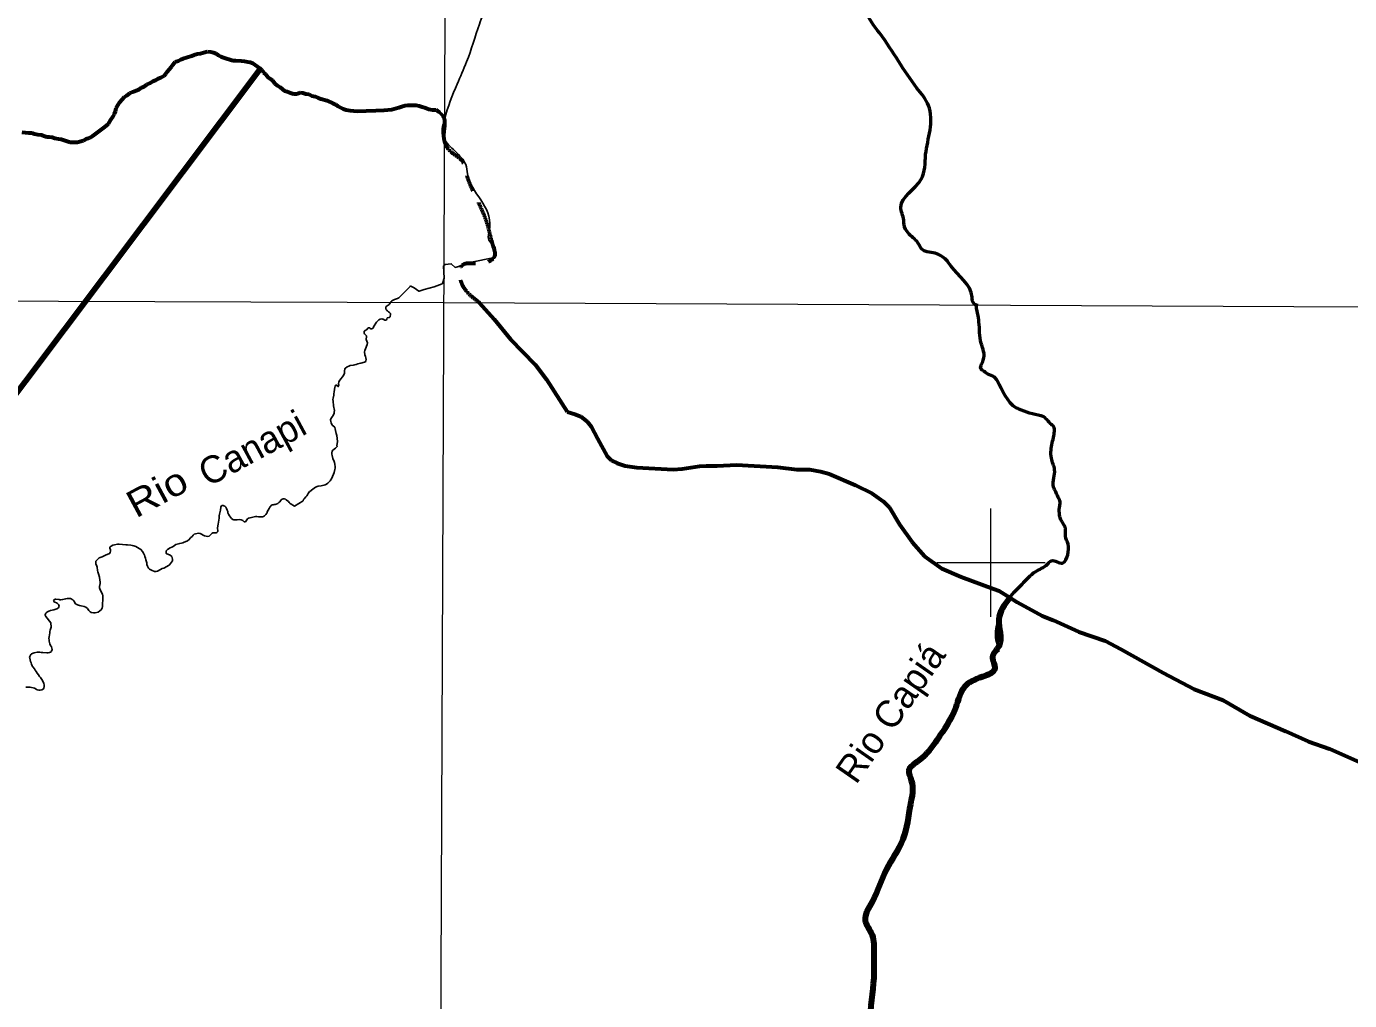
# Model space of a CAD drawing. Extents: x 553962 to 842807, y 8883888 to 9032388.
# Drawn here: x 657184 to 681625, y 8991910 to 9009903 of the extents above; entities that cross this region are included whole.
import ezdxf
from ezdxf.enums import TextEntityAlignment as Align

# ---------------------------------------------------------------- set-up
doc = ezdxf.new("R2010")
doc.units = 0
doc.header["$LTSCALE"] = 200
doc.linetypes.add('LONG_DASH_SHORT_DASH', pattern=[9.9, 6, -1.2, 1.5, -1.2])
for name, color, linetype, lineweight in [('1', 7, 'Continuous', 13), ('2', 7, 'Continuous', 13), ('24', 7, 'Continuous', 25), ('7', 7, 'LONG_DASH_SHORT_DASH', 60), ('9', 7, 'Continuous', 90)]:
    doc.layers.add(name, color=color, linetype=linetype, lineweight=lineweight)
doc.layers.add('49', color=7, linetype='Continuous')

msp = doc.modelspace()

# ---------------------------------------------------------------- linework, layer by layer
at = {"layer": '1'}
for points in [[(664968.2, 9023436.8), (664657.1, 8949509), (664397.1, 8890880.2)], [(565303.2, 9005146.6), (664889.8, 9004806.7), (719872.1, 9004543.9), (790635.8, 9004109)]]:
    msp.add_lwpolyline(points, dxfattribs=at)
at = {"layer": '2'}
for p, q in [((675000, 8999000), (675000, 9001000)), ((674000, 9000000), (676000, 9000000))]:
    msp.add_line(p, q, dxfattribs=at)
at = {"layer": '24'}
for points in [[(664888.7, 9005478.8), (664900.1, 9005251.2), (664869.8, 9005153.3), (664865.4, 9005145.8), (664717.4, 9005095.4), (664528.5, 9005045), (664441.2, 9005012.7), (664432.8, 9005015.5), (664343.5, 9005072.6), (664286.2, 9005107.2), (664280.8, 9005109), (664271.5, 9005101.5), (664208.7, 9005038.3), (664080.1, 9004905.7)], [(665798.1, 9005626.6), (665405.1, 9005550.8), (665165.6, 9005466.5), (665101.5, 9005450.6), (665032.2, 9005519.9), (664921.3, 9005506.1), (664888.7, 9005478.8)], [(664080.1, 9004905.7), (664063.5, 9004888.7), (664040.8, 9004876.6), (664021.9, 9004870), (663980.2, 9004861.2), (663946.3, 9004843.8), (663931.6, 9004832.2), (663929.7, 9004827.5), (663925.3, 9004825.6), (663922.8, 9004820.1), (663917.9, 9004815.5), (663910.5, 9004801.1), (663899, 9004783.8), (663883.9, 9004765), (663863.8, 9004751.9), (663845.5, 9004742.3), (663830.7, 9004729.4), (663824.8, 9004721.3), (663819.7, 9004702.6), (663823.3, 9004691.5), (663824.1, 9004683.3), (663832.8, 9004668.7), (663842.4, 9004656.8), (663854.1, 9004648.1), (663869.6, 9004633.8), (663887.6, 9004620.7), (663907, 9004598.9), (663907, 9004598.9), (663910.9, 9004584.5), (663902.4, 9004543.4), (663900.7, 9004539.3), (663881.2, 9004529), (663848.8, 9004520.2), (663839.5, 9004493.6), (663833.8, 9004483.1), (663820.7, 9004477), (663803.2, 9004478.8), (663774.4, 9004497.4), (663769.2, 9004499), (663746.7, 9004499.8), (663720.6, 9004496.7), (663695.8, 9004484.7), (663668.4, 9004461.3), (663648.1, 9004440.9), (663597.4, 9004352.2)], [(663597.4, 9004352.2), (663591.9, 9004338.7), (663585.2, 9004327.5), (663562, 9004318.3), (663545.8, 9004318.1), (663534.7, 9004324.6), (663525, 9004333.9), (663497.8, 9004335.9), (663473.3, 9004304.2), (663451.5, 9004291.8), (663425.3, 9004274.1), (663419.2, 9004251.7), (663419.6, 9004240.3), (663428.8, 9004227), (663461.2, 9004195.3), (663463.7, 9004190.3), (663466.9, 9004175.9), (663457.9, 9004121.1), (663483.9, 9004058.1), (663479.5, 9004030.4), (663444.7, 9003947.7), (663436.1, 9003919.8), (663430, 9003892.9), (663436.2, 9003836.4), (663444.6, 9003808.5), (663450.1, 9003780.8), (663459.3, 9003752.9), (663454.4, 9003726), (663450.1, 9003716.1), (663431.3, 9003702.2), (663360.9, 9003681.5), (663332.3, 9003676.8), (663305.3, 9003670.6), (663276.6, 9003659.9), (663248.8, 9003653.3), (663221, 9003644.9), (663165.3, 9003637.2), (663137.5, 9003629.7), (663109.8, 9003617.9), (663077.1, 9003593.6), (663073.8, 9003588.8), (663066.6, 9003572.2), (663061.7, 9003539.8), (663061.5, 9003511.9), (663059.4, 9003496.8), (663040.9, 9003457.1), (662971.2, 9003371.5), (662951.9, 9003338.4), (662948.3, 9003299.8), (662954, 9003282), (662947.1, 9003264.8), (662944, 9003251.6), (662942.9, 9003251.1), (662911.9, 9003278.6), (662899.6, 9003277.8), (662888.3, 9003260.5), (662879.6, 9003232.8), (662873.2, 9003204.9), (662866.8, 9003150.2), (662861.5, 9003121.4), (662858.9, 9003091.8), (662849.7, 9003038), (662846.5, 9003010.2), (662846.6, 9002979.2), (662855.1, 9002895.8), (662859.3, 9002866.8), (662868.7, 9002836.8), (662871.9, 9002808.7), (662871, 9002777.8), (662869.2, 9002761.2), (662849.1, 9002718.3), (662831.4, 9002691.2), (662805.1, 9002656.3), (662801.6, 9002634.7), (662804.8, 9002607.8), (662812, 9002578.7), (662832, 9002539.4), (662877.8, 9002502.9), (662881.5, 9002497.6), (662889.1, 9002470.7), (662893.7, 9002439.9), (662905.9, 9002382.7), (662915.2, 9002349), (662932.3, 9002238.2)], [(662932.3, 9002238.2), (662930.4, 9002232.8), (662918.7, 9002162.2), (662919.1, 9002158.4), (662924.3, 9002149.5), (662924.7, 9002146.9), (662910.5, 9002130.5), (662890.5, 9002112.2), (662844.9, 9002076.1), (662830.6, 9002055.4), (662824.1, 9002025.5), (662826.1, 9001999.9), (662830.2, 9001975), (662842.8, 9001924.6), (662865.6, 9001868.5), (662873.1, 9001845.7), (662878.6, 9001819.2), (662886, 9001766.9), (662885.8, 9001743), (662880.8, 9001718.2), (662866.3, 9001665.2), (662823, 9001561.5), (662795.5, 9001511.2), (662776.8, 9001488.3), (662751.1, 9001464.8), (662727, 9001447.9), (662703, 9001435.9), (662679.1, 9001427.9), (662625.9, 9001415.6), (662573.7, 9001409.9), (662524, 9001394.2), (662471, 9001354.5)], [(662471, 9001354.5), (662418, 9001314.7), (662413.9, 9001313.1), (662387.4, 9001275.2), (662375.4, 9001250.8), (662363.1, 9001233.2), (662344.9, 9001211.6), (662312, 9001177.4), (662303.6, 9001164.2), (662297.6, 9001142.3), (662132.9, 9001044.6), (662055.9, 9001090.7), (662051.5, 9001092.1), (662048.6, 9001095.2), (662046.8, 9001099.7), (662037.3, 9001108.4), (662022.2, 9001125.4), (661983.8, 9001159.7), (661966.6, 9001172.4), (661944.8, 9001178.8), (661926.5, 9001177.5), (661909.8, 9001173.8), (661901.4, 9001170.2), (661890.7, 9001159.3), (661864.8, 9001124.2), (661848.9, 9001108.4), (661829.4, 9001092.8), (661799.7, 9001079.5), (661781.2, 9001073.3), (661761.2, 9001070.8), (661742.7, 9001066.8), (661725.3, 9001066.6), (661721.3, 9001065.5), (661706.2, 9001054.2), (661685.2, 9001030.2), (661683.4, 9001024.9), (661678.4, 9001021.4), (661666.2, 9000995.9)], [(661666.2, 9000995.9), (661666, 9000995.8), (661628.2, 9000939.1), (661629.1, 9000923.3), (661621.8, 9000911.6), (661602.7, 9000889), (661580.6, 9000865.8), (661565.2, 9000853.8), (661545, 9000847.3), (661519.3, 9000842.1), (661468.8, 9000846.1), (661442.2, 9000850.3), (661414.8, 9000850.2), (661390.9, 9000847.2), (661313.8, 9000829), (661288.2, 9000820.3), (661264.1, 9000805.4), (661227.5, 9000755.1), (661208, 9000751.3), (661198.2, 9000757.5), (661179.9, 9000776.4), (661150.3, 9000789.5), (661123.7, 9000793.6), (661075.9, 9000790.6), (661048.4, 9000786.4), (661015, 9000789.2), (660997, 9000798), (660969.6, 9000815.2), (660936.1, 9000861.2), (660916.9, 9000893.2), (660906.5, 9000918), (660902.7, 9000944.6), (660893.5, 9000969.5), (660880.3, 9000995.9), (660864.7, 9001020.9), (660846.7, 9001041.3), (660832.8, 9001051.1), (660807.4, 9001057.7), (660797.2, 9001057), (660783.2, 9001044), (660772.5, 9001021.6), (660765.5, 9000968.5), (660747.9, 9000894.1), (660744.4, 9000865.7), (660743.2, 9000816.2), (660736.9, 9000789.6), (660730.5, 9000739.1), (660724.1, 9000712.6), (660715.8, 9000638.2), (660717.6, 9000586.8), (660716.8, 9000576.4), (660703.4, 9000556.3), (660691.2, 9000550.9), (660651.6, 9000550.6), (660627.7, 9000547.6), (660617, 9000544), (660613.3, 9000541.4), (660580.1, 9000504.8), (660556, 9000490), (660529.6, 9000484.5), (660503.9, 9000484.7), (660470.1, 9000491.9), (660394.1, 9000535.8), (660385, 9000538.7), (660360.5, 9000540.9), (660309.2, 9000533.2), (660284.4, 9000522.9), (660273.5, 9000516.3)], [(660273.5, 9000516.3), (660260.7, 9000503.6), (660242.4, 9000482.3), (660221.6, 9000464.5), (660179.6, 9000416.4), (660146.5, 9000396.3), (660098.7, 9000374.4), (660070.2, 9000365.5), (660046.2, 9000355.7), (660017.1, 9000352.3), (659968.3, 9000340.1), (659941.1, 9000330.8), (659916.1, 9000316.3), (659891.5, 9000299.3), (659868.5, 9000285.3), (659840.5, 9000274.1), (659791.5, 9000243.5), (659791.5, 9000243.5), (659764.1, 9000216.7)], [(659764.1, 9000216.7), (659766.6, 9000170.3), (659768.2, 9000165.1), (659774.5, 9000160.6), (659826.5, 9000142.5), (659840.8, 9000136.1), (659866.7, 9000114.8), (659877.4, 9000088.4), (659881.6, 9000062.4), (659881.8, 9000044.3), (659878.7, 9000033.4), (659825.5, 8999960), (659819.5, 8999953.8), (659723.2, 8999895.5), (659688.5, 8999887.8), (659659.7, 8999873.4), (659605.7, 8999841.4), (659576.1, 8999832.9), (659549.3, 8999836.2), (659494.5, 8999857.3), (659459.2, 8999876.8), (659440.5, 8999897.3), (659416.9, 8999934), (659408.9, 8999962.1), (659405.4, 8999993), (659391.8, 9000051.2), (659380, 9000082), (659373.4, 9000111.9), (659363.4, 9000140), (659357.1, 9000148.2), (659344.6, 9000173.6), (659327.4, 9000201.8), (659297.2, 9000242.3), (659268.6, 9000258.6), (659204.1, 9000299.8), (659165.9, 9000310.6), (659139.1, 9000316.3), (659110, 9000320.5), (659049.2, 9000326.1), (659018.4, 9000330.3), (658960.2, 9000334.5), (658898.5, 9000340.9), (658868.6, 9000338.6), (658809.5, 9000327), (658781.4, 9000320), (658750.4, 9000304), (658731.6, 9000292.7), (658725, 9000283.2), (658721, 9000274), (658723.2, 9000264.3), (658735.2, 9000237.8), (658736.5, 9000212.6), (658728.3, 9000183.5), (658719.9, 9000170.5), (658646.8, 9000134.5), (658582.1, 9000107.9), (658527.1, 9000087.1), (658500.7, 9000063.1), (658466.8, 9000023.7), (658464.3, 9000011.6), (658467.1, 8999971.4), (658475.8, 8999953.7), (658488.4, 8999914.2), (658494.9, 8999855.1), (658500.1, 8999826), (658513.6, 8999793.3), (658531.7, 8999732.1), (658538.8, 8999675.3), (658544, 8999643.4), (658543.9, 8999614.5), (658535.6, 8999557.6), (658535.5, 8999531.6), (658542.9, 8999498.1), (658590.6, 8999417.1), (658596.3, 8999388.5), (658593.3, 8999333.7), (658594.3, 8999302.9), (658591.1, 8999245.1), (658587, 8999215.1), (658587.8, 8999186), (658581.9, 8999159.2), (658571.8, 8999140.2), (658561.5, 8999126.8), (658537.9, 8999105.5), (658506.5, 8999084.8), (658451.1, 8999073.9), (658421.2, 8999073.9), (658391.5, 8999076.1), (658380.9, 8999077.9), (658363.2, 8999087.9), (658334.8, 8999114.2), (658310.6, 8999148.7), (658278.5, 8999178.4), (658249.9, 8999187.4), (658191.8, 8999200), (658161.8, 8999208.5), (658129.2, 8999220.1), (658104, 8999230.8), (658091.6, 8999239.2), (658060.2, 8999290.2), (658040.3, 8999310.8)], [(658040.3, 8999310.8), (658040.3, 8999310.8), (658000, 8999337.8), (657966.4, 8999338.9), (657938.3, 8999334), (657908.4, 8999330.6), (657878.4, 8999322.2), (657850.3, 8999317.1), (657817.7, 8999313.6), (657800.3, 8999313.7), (657787.5, 8999316.9), (657729.5, 8999326.2), (657712.2, 8999324.4), (657688.6, 8999307.5), (657685.1, 8999292.1), (657687.3, 8999285.1), (657693, 8999275.8), (657753.2, 8999252.7), (657775, 8999226.5), (657782.3, 8999211.3), (657785.2, 8999193), (657784.6, 8999178.2), (657773.8, 8999165.3), (657744.9, 8999144), (657690.9, 8999127.6), (657660.1, 8999123), (657630.1, 8999116.6), (657595.5, 8999103.3), (657562.7, 8999084.1), (657548.4, 8999069.4), (657544.1, 8999063.3), (657530.6, 8999033.5), (657531.1, 8999026), (657541, 8999005.5), (657634.2, 8998884.3), (657639.8, 8998808), (657621.8, 8998753.6), (657615.4, 8998727.9), (657612.9, 8998701.4), (657601.6, 8998627.3), (657600.2, 8998596.8), (657601.2, 8998573), (657604.3, 8998548.1), (657616.1, 8998496.8), (657628.2, 8998469.8), (657644.2, 8998443.7), (657653.9, 8998417.1), (657657.6, 8998393.2), (657648.4, 8998365.3), (657644.6, 8998359), (657626.4, 8998346.5), (657609.5, 8998339.4), (657584.9, 8998335.4), (657557.6, 8998334.5), (657484.2, 8998341.6), (657456.7, 8998341.8), (657430.2, 8998343.8), (657405.3, 8998342.9), (657378.8, 8998343.7), (657329.2, 8998335.4), (657279.9, 8998312.1), (657261.7, 8998299.4), (657250.3, 8998279.6), (657242.8, 8998249.8), (657243.3, 8998231.8), (657260.7, 8998173.6), (657272.5, 8998147), (657279.3, 8998120.5), (657289.5, 8998090.3), (657298.5, 8998083.2), (657303.2, 8998074.5), (657330.3, 8998035.7), (657345, 8998010.8), (657364.6, 8997987.5), (657384, 8997954.4), (657403.7, 8997929), (657426.3, 8997895.3), (657445.7, 8997875.4), (657467.3, 8997843.1), (657480.4, 8997819), (657504, 8997765.2), (657512, 8997741.1), (657513.1, 8997712.8), (657507.4, 8997682.2), (657504.9, 8997678.3), (657489.8, 8997663.3), (657464.9, 8997646.8), (657439.6, 8997643), (657411, 8997643.7), (657379.6, 8997651.8), (657363.8, 8997663.7), (657331.7, 8997680.8), (657249.9, 8997700.5), (657175.3, 8997701)]]:
    msp.add_lwpolyline(points, dxfattribs=at)
at = {"layer": '24', "lineweight": 53}
for points in [[(674726.7, 9004751), (674666.6, 9004817.9), (674653.2, 9004904.8), (674258.7, 9005480.2), (674171.8, 9005593.9), (674084.9, 9005660.8), (673971.2, 9005714.3), (673824.1, 9005741.1), (673750.6, 9005767.8), (673650.3, 9005908.3), (673469.7, 9006089), (673396.2, 9006242.8), (673389.5, 9006323.1), (673336, 9006563.9), (673714.2, 9007080), (673794.5, 9007534.9), (673874.7, 9007989.8), (673848, 9008444.8), (673634, 9008765.9), (672938.7, 9009782.8), (672724.7, 9010157.4), (673339.8, 9010746.1), (673527, 9010906.7), (673874.7, 9011040.5), (674008.4, 9011227.8), (673874.7, 9011896.8), (673981.7, 9012137.6), (674115.4, 9012271.4), (674222.4, 9012699.6), (673848, 9012699.6), (673500.3, 9012967.2), (672751.4, 9012886.9), (672564.2, 9013208), (672377, 9013341.8), (672243.3, 9013796.7), (672109.6, 9013957.3), (671868.9, 9014171.4), (671869.6, 9014455.6), (671949.9, 9014696.4), (672110.3, 9015231.6), (672244.1, 9015633), (672190.6, 9015820.4), (671869.6, 9015847.1), (671762.7, 9016088), (671495.2, 9016248.5), (671441.7, 9016596.4), (671094.1, 9016623.2), (670505.7, 9016837.2), (670211.5, 9016971), (670024.3, 9017265.4)], [(675154.1, 8998412.8), (675100.6, 8998680.4), (675187.5, 8999035), (675307.8, 8999295.9), (675575.3, 8999603.6), (675822.7, 8999831.1), (676043.3, 8999971.6), (676116.8, 9000031.8), (676324.1, 8999991.6), (676417.7, 9000145.5), (676424.4, 9000339.5), (676377.6, 9000486.7), (676377.6, 9000627.2), (676357.6, 9000680.7), (676277.3, 9000827.9), (676264, 9000914.9), (676270.6, 9001048.7), (676277.3, 9001122.2), (676243.9, 9001202.5), (676183.7, 9001339.3), (676157, 9001392.8), (676163.7, 9001566.7), (676177, 9001713.9), (676116.8, 9001928), (676110.2, 9002075.2), (676130.2, 9002209), (676163.7, 9002342.8), (676170.3, 9002389.6), (676150.3, 9002523.4), (676116.8, 9002550.2), (675949.7, 9002704), (675923, 9002710.7), (675515.1, 9002833.7), (675475, 9002853.7), (675113.9, 9003362.2), (675067.1, 9003422.4), (674940.1, 9003482.6), (674859.8, 9003542.8), (674819.7, 9003569.6), (674859.8, 9003736.8), (674819.7, 9004051.2), (674779.6, 9004439.2), (674752.9, 9004606.5), (674739.5, 9004773.7), (674742.2, 9004781.9)], [(673192.8, 8986819.2), (673266.9, 8987063), (672967.2, 8987378.4), (672888.4, 8987819.9), (673046.1, 8988482.3), (673345.7, 8989160.4), (673503.4, 8989586.2), (673377.3, 8989901.6), (673046.1, 8990153.9), (673014.5, 8990469.3), (673109.2, 8990705.9), (673156.5, 8990942.4), (672983, 8991115.9), (672793.8, 8991510.2), (672841.1, 8992330.2), (672841.1, 8992787.6), (672809.5, 8993118.7), (672683.4, 8993386.8), (672809.5, 8993733.8), (673077.6, 8994335.6), (673377.3, 8994887.9), (673519.2, 8995534.8), (673535, 8995976.6), (673487.7, 8996159.6), (673676.9, 8996349), (674008.1, 8996727.7), (674355, 8997327.2), (674512.7, 8997705.9), (674843.9, 8997895.2), (675080.4, 8998053), (675033.1, 8998242.4), (675144.3, 8998385.5)]]:
    msp.add_spline(points, degree=3, dxfattribs=at)
at = {"layer": '24'}
msp.add_spline([(665804.3, 9005643.1), (665835.9, 9005832.9), (665741, 9005927.8), (665741, 9006196.7), (665330, 9007177.5), (665298.4, 9007351.5), (665219.3, 9007478.1), (664982.2, 9007715.4), (664887.3, 9007841.9), (664903.2, 9008190), (665140.3, 9008838.5), (665314.2, 9009249.8), (665551.3, 9009945.9), (665693.6, 9010293.9), (665962.4, 9010752.7), (666088.8, 9010942.5), (666468.3, 9011179.8), (666547.3, 9011306.3), (666847.7, 9011844.2), (667100.6, 9012508.6), (667369.4, 9012714.2), (667733, 9012603.5)], degree=3, dxfattribs=at)
at = {"layer": '7'}
for points in [[(659209.3, 9008717), (659256.9, 9008739.8), (659309.5, 9008775.2), (659357.1, 9008795.4), (659404.7, 9008830.8), (659464.8, 9008856.2), (659519.9, 9008891.6), (659567.5, 9008909.3), (659615.1, 9008942.2), (659667.8, 9008962.5), (659725.4, 9008992.9), (659757.9, 9009030.7), (659787.8, 9009070.9), (659822.9, 9009106.2), (659865.3, 9009159.1), (659892.8, 9009199.4), (659930.3, 9009247.3), (659990.4, 9009270.1), (660038.1, 9009290.4), (660080.7, 9009313.2), (660236.1, 9009361.6), (660281.2, 9009379.3), (660341.4, 9009397.2), (660401.7, 9009402.5), (660459.3, 9009422.8), (660527.1, 9009438.2), (660589.8, 9009435.9), (660637.6, 9009421.1), (660685.4, 9009403.7), (660723.1, 9009373.8), (660773.5, 9009346.4), (660826.2, 9009326.5), (660997.2, 9009272.1), (661049.9, 9009272.3), (661152.8, 9009267.7), (661210.6, 9009263), (661270.9, 9009248.2), (661318.6, 9009243.4), (661363.9, 9009226), (661409.2, 9009193.6), (661452, 9009166.2), (661492.3, 9009133.7), (661532.6, 9009096.2), (661560.4, 9009051.2), (661608.2, 9009013.8), (661641.1, 9008966.2), (661691.4, 9008936.3), (661729.2, 9008903.9), (661774.6, 9008851.3), (661814.9, 9008811.4), (661867.8, 9008781.5), (661950.8, 9008716.6), (661998.6, 9008701.8), (662059, 9008674.4), (662116.8, 9008659.6), (662177, 9008659.9), (662242.2, 9008680.2), (662289.9, 9008675.4), (662347.7, 9008658.1), (662403, 9008653.3), (662458.3, 9008623.5), (662518.6, 9008606.2), (662574, 9008583.8), (662624.2, 9008566.5), (662734.8, 9008536.9), (662850.5, 9008479.7), (662898.3, 9008462.3), (662936.1, 9008432.3), (663034.2, 9008380.1), (663089.5, 9008362.8), (663162.3, 9008348), (663225.1, 9008343.3), (663290.4, 9008341.1), (663458.6, 9008341.8), (663636.8, 9008352.6), (663792.4, 9008358.3), (663932.9, 9008369), (664063.3, 9008404.7), (664121, 9008425.1), (664178.6, 9008442.9), (664231.3, 9008448.1), (664334.2, 9008448.6), (664384.5, 9008446.3), (664439.7, 9008439), (664492.5, 9008419.2), (664552.8, 9008401.9), (664615.7, 9008374.6), (664683.5, 9008364.8), (664748.7, 9008365.1)], [(657098.1, 9007949.5), (657221.2, 9007940.1), (657283.9, 9007937.8), (657331.7, 9007920.5), (657392, 9007908.2), (657459.9, 9007898.4), (657505.1, 9007881.1), (657557.9, 9007866.2), (657605.6, 9007861.4), (657655.9, 9007859.2), (657708.7, 9007841.8), (657776.5, 9007827.1), (657824.2, 9007822.2), (657990.2, 9007767.8), (658125.8, 9007768.4), (658236.1, 9007799), (658286.2, 9007829.3), (658346.4, 9007847.2), (658409, 9007885.1), (658461.6, 9007920.5), (658634.4, 9008049.3), (658702, 9008104.8), (658744.3, 9008180.3), (658786.8, 9008240.7), (658809.2, 9008288.5), (658826.6, 9008333.8), (658841.4, 9008396.6), (658876.3, 9008457), (658911.3, 9008504.8), (658993.8, 9008600.6), (659038.9, 9008628.4), (659096.5, 9008668.8), (659149.1, 9008696.6), (659209.3, 9008717)], [(665554.2, 9004795.8), (665826.3, 9004496), (666128.4, 9004129.5), (666582.2, 9003656.2), (666791.2, 9003384.4), (667173.5, 9002782.6), (667316.8, 9002742.9), (667422.9, 9002700.1), (667541.5, 9002608.8), (667614.9, 9002511.4), (667732.4, 9002291), (667913.5, 9001963.7), (667993.5, 9001885.6), (668093.1, 9001836.3), (668244.3, 9001789.9), (668460.2, 9001759), (669127.8, 9001717.8), (669295.7, 9001729.2), (669615.5, 9001778.1), (669741.5, 9001789.9), (669941.5, 9001784.9), (670299.8, 9001804.4), (671060.9, 9001759.2), (671415.5, 9001717.4), (671657.5, 9001718.6), (671854, 9001684.6), (672015, 9001638.1), (672500.4, 9001430.7), (672799.2, 9001283), (673014.1, 9001129.5), (673119.7, 9001025.4), (673313.7, 9000701.2), (673543.2, 9000376.6), (673773.3, 9000119.8), (674094, 8999888.1), (674450.8, 8999736.6), (675045.9, 8999515.4), (675152, 8999479), (675299.7, 8999387.4), (675485.8, 8999269.7), (675948.3, 8999017.4), (676147.6, 8998938.2), (676626.5, 8998721.2), (677112.3, 8998555.8), (677401.4, 8998398.5), (678181.7, 8997966), (678753.5, 8997661.1), (679287.3, 8997456.5), (679791.4, 8997168.3), (680440.8, 8996888.6), (680868.3, 8996697.8), (681254.3, 8996559), (681874.7, 8996282.7)]]:
    msp.add_lwpolyline(points, dxfattribs=at)
msp.add_spline([(664746.7, 9008367.1), (664889.8, 9008223.9), (664889.8, 9007865.9), (665018.7, 9007593.8), (665247.7, 9007393.2), (665290.6, 9007250), (665362.2, 9007020.9), (665634.2, 9006419.4), (665748.7, 9006047), (665806, 9005832.2), (665834.6, 9005674.7), (665634.2, 9005531.4), (665219.1, 9005474.2), (665190.4, 9005273.6), (665554.2, 9004795.8)], degree=3, dxfattribs=at)
at = {"layer": '9'}
msp.add_lwpolyline([(635350.7, 8977923.9), (636116.8, 8981777.4), (642228, 8989744.8), (647160.3, 8990514), (649828, 8995545.6), (655722.5, 9001435.5), (661506.7, 9009120.3)], dxfattribs=at)
msp.add_spline([(673192.8, 8986819.2), (673266.9, 8987063), (672967.2, 8987378.4), (672888.4, 8987819.9), (673046.1, 8988482.3), (673345.7, 8989160.4), (673503.4, 8989586.2), (673377.3, 8989901.6), (673046.1, 8990153.9), (673014.5, 8990469.3), (673109.2, 8990705.9), (673156.5, 8990942.4), (672983, 8991115.9), (672793.8, 8991510.2), (672841.1, 8992330.2), (672841.1, 8992787.6), (672809.5, 8993118.7), (672683.4, 8993386.8), (672809.5, 8993733.8), (673077.6, 8994335.6), (673377.3, 8994887.9), (673519.2, 8995534.8), (673535, 8995976.6), (673487.7, 8996159.6), (673676.9, 8996349), (674008.1, 8996727.7), (674355, 8997327.2), (674512.7, 8997705.9), (674843.9, 8997895.2), (675080.4, 8998053), (675033.1, 8998242.4), (675150.3, 8998458.4), (675150.3, 8998951.2), (675361.3, 8999361.8)], degree=3, dxfattribs=at)

# ---------------------------------------------------------------- texts
at = {"layer": '49'}
for s, rotation, p in [('Canapi', 28.393, (661469, 9001892.9)), ('Rio Capiá', 55.175, (673347.5, 8997088.6))]:
    msp.add_text(s, height=500, rotation=rotation, dxfattribs=at).set_placement(p, align=Align.CENTER)
at = {"layer": '49', "width": 1.15}
msp.add_text('Rio', height=500, rotation=28.393, dxfattribs=at).set_placement((659714, 9001085.8), align=Align.CENTER)

doc.saveas('drawing.dxf')
